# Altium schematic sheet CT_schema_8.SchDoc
size 368 x 245 mm
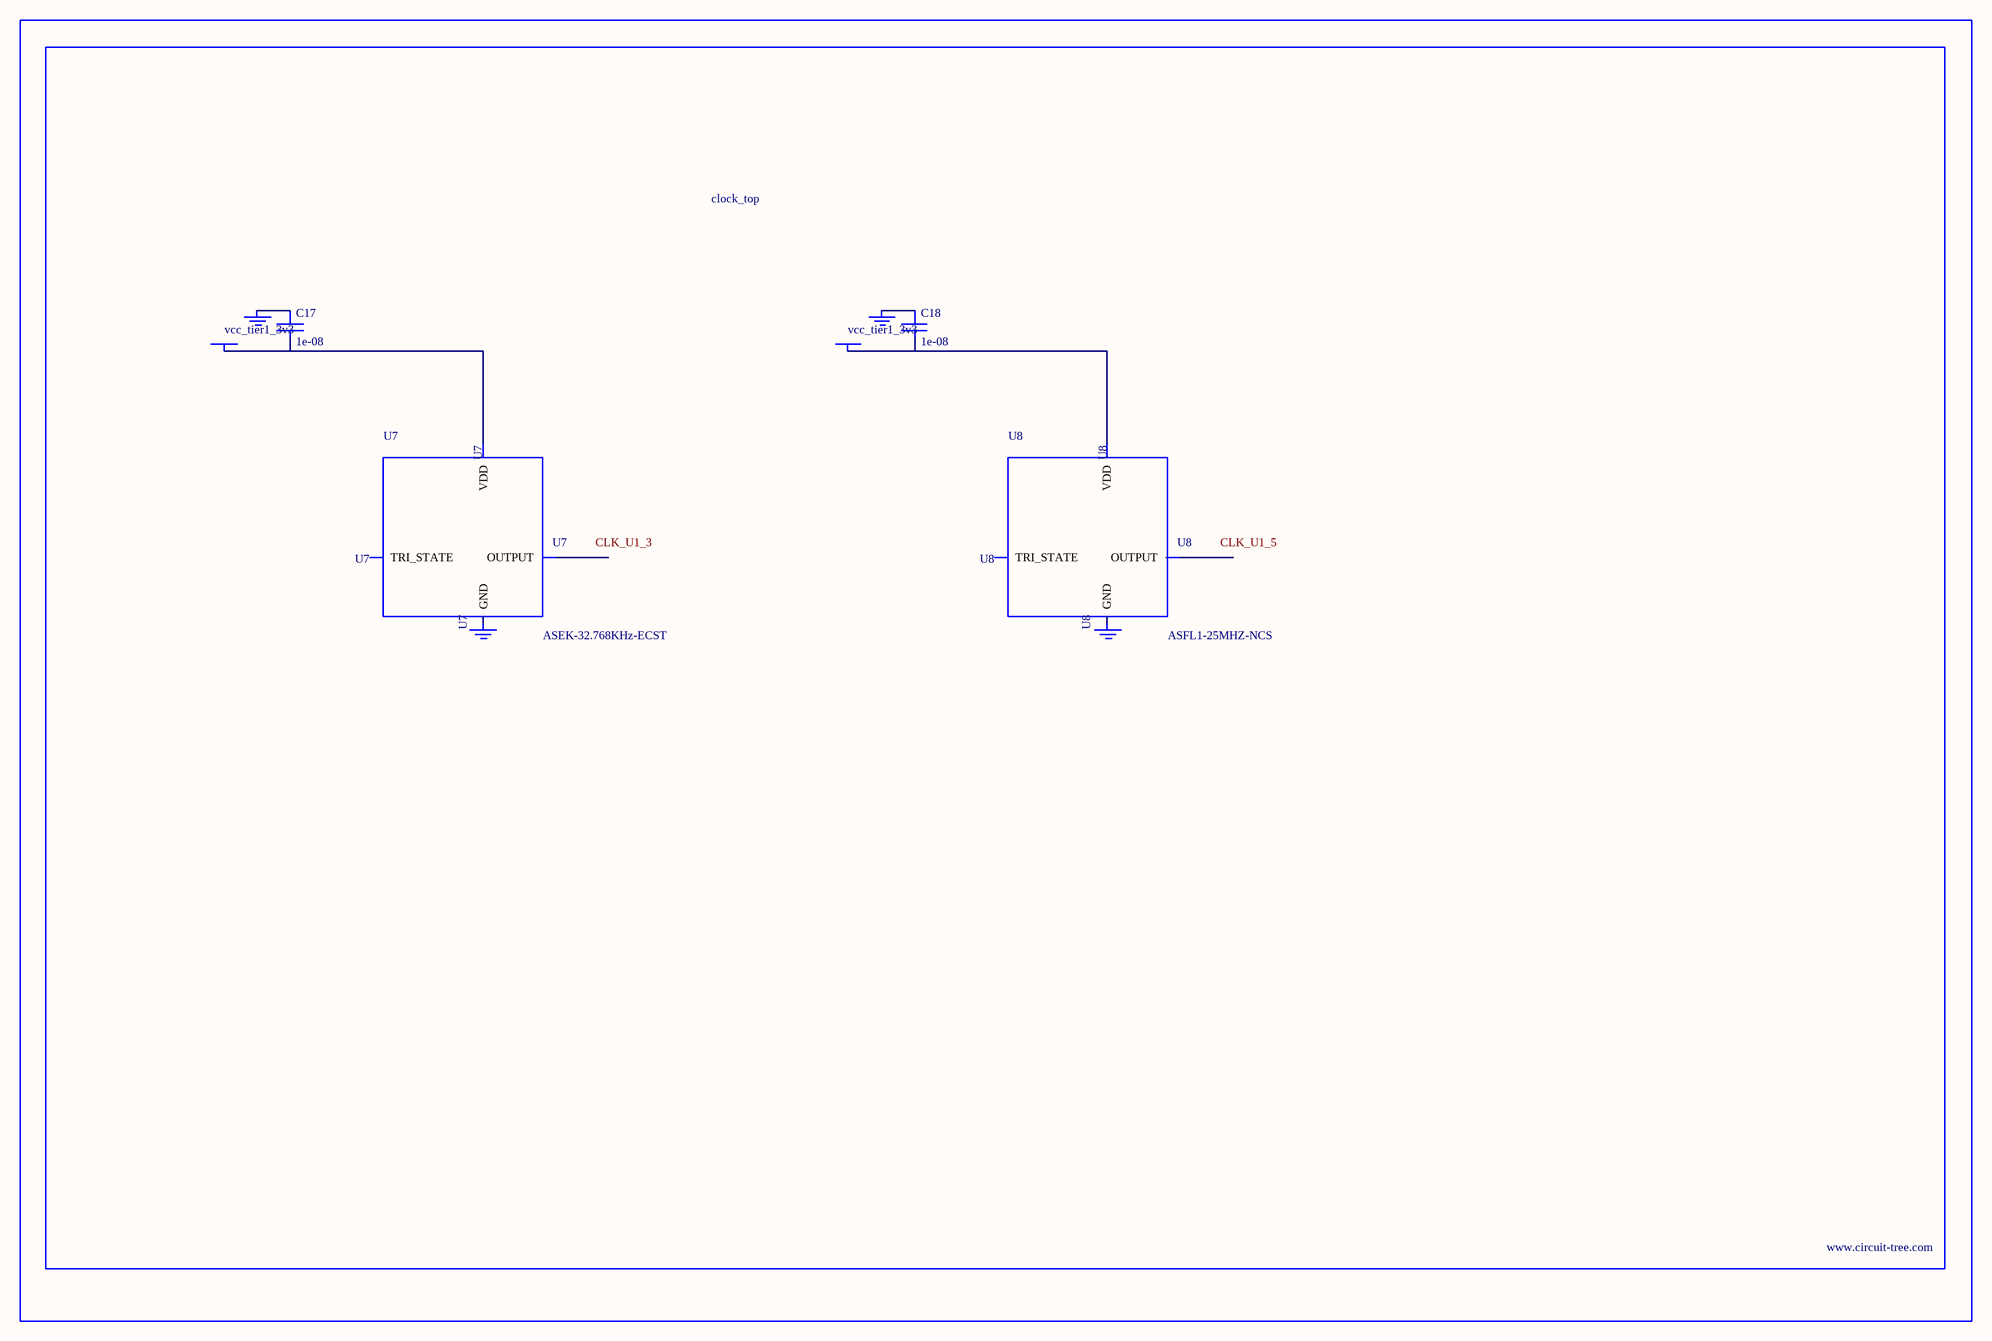
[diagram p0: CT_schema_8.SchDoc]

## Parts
BORDER7  (no value)
C17  1e-08  [C0402]
C18  1e-08  [C0402]
GND_INSTANCE_7_0  (no value)
GND_INSTANCE_7_1  (no value)
GND_INSTANCE_7_2  (no value)
GND_INSTANCE_7_3  (no value)
POWER_INSTANCE_7_0  vcc_tier1_3v3
POWER_INSTANCE_7_1  vcc_tier1_3v3
U7  ASEK-32.768KHz-ECST  [ASEK]
U8  ASFL1-25MHZ-NCS  [ASFL1]

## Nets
NetC17_1: C17.1 GND_INSTANCE_7_0.0(GND)
NetC17_2: C17.2 POWER_INSTANCE_7_0.0(PWR) U7.4(VDD)
NetC18_1: C18.1 GND_INSTANCE_7_2.0(GND)
NetC18_2: C18.2 POWER_INSTANCE_7_1.0(PWR) U8.4(VDD)

Not connected (* = marked no-connect by the designer): GND_INSTANCE_7_1 0(GND); GND_INSTANCE_7_3 0(GND); U7 1(TRI_STATE) 2(GND) 3(OUTPUT); U8 1(TRI_STATE) 2(GND) 3(OUTPUT)

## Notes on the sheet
- Labels drawn without touching a wire or pin: CLK_U1_3, CLK_U1_5

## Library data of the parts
BORDER7 = BORDER_PAGE7
C17 C18 = C0402C103K3RAC
GND_INSTANCE_7_0-GND_INSTANCE_7_3 = GND
POWER_INSTANCE_7_0 POWER_INSTANCE_7_1 = PWR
